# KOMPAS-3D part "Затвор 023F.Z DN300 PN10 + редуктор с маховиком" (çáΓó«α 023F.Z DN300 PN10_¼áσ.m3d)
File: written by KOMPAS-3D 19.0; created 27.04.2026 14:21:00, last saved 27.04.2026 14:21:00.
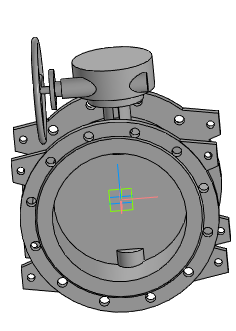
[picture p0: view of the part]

Document properties: Полное имя файла: ..\..\Затвор 023F.Z DN200-DN1600_с маховиком\Затвор 023F.Z DN300 PN10 + редуктор с маховиком.a3d

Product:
- Part/product: Затвор 023F.Z DN300 PN10 + редуктор с маховиком
    Масса: 96.6341

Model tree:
1. Операция без истории:1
